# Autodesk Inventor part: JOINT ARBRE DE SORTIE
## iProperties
Created: 2004-11
Part Number: JOINT ARBRE DE SORTIE
Document SubType Name: Modeling
Designer: Bruno
Manufacturer: Standard
Standards Organization: Custom
Author: Bruno
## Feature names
1. Base1
